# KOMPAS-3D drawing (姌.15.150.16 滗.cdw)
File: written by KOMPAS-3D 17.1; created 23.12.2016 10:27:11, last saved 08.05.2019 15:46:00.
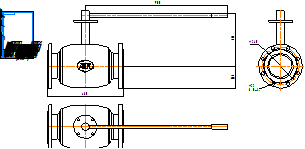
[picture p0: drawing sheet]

Sheet 1: A4, portrait

Title block, sheet 1: name: КШ.15.150.16 фф; material: Внимание! Данный продукт является объектом авторского права ООО «Торговый Дом АДЛ». / Запрещается изменение, копирование, распространение / (в том числе путем копирования на другие сайты и ресурсы в Интернете) / или любое иное использование информации и объектов без предварительного / согласия правообладателя (ООО «Торговый Дом АДЛ»).; sheets: 1; organisation: ООО "Торговый дом АДЛ"; sheet format: A4; stored path: C:\Users\tra\Desktop\2д чертежи\Шаровые краны БИВАЛ\КШ_Бивал_серия_14_15\KOMPAS_2D\КШ.15.150.16 фф.cdw

Views: Вид 1, Проекционный вид 2, Проекционный вид 3
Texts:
  Klimkovich
  ADL
Dimensions and other numbers on the sheet: 480; 900; 336; 140; 240; 22; 8 Отв.; 1:1; 1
